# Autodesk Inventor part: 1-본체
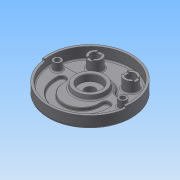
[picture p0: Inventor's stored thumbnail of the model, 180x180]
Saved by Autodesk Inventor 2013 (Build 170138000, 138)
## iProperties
Created: 2015-06
Part Number: 1-본체
Material: 일반
Document SubType Name: Modeling
Designer: Administrator
Density: 1 g/cm^3
Author: Administrator
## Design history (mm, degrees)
sketch "스케치1"
  geometry: C1 r 95 at (0, 0); 1 further point
  constraints: 1 centre point, 1 coincident
  dimensions: "d0" = 190 diameter of C1
extrude "돌출1" new body sketch "스케치1" distance "d2" = 32; taper "d3" = 0 deg
sketch "스케치2"
  geometry: C1 r 95 at (0, 0) reference; C2 r 90 at (0, 0)
  constraints: 1 centre point, 1 coincident
  dimensions: "d4" = 180 diameter of C2
extrude "돌출2" cut sketch "스케치2" distance "d6" = 18; taper "d7" = 0 deg
sketch "스케치3"
  geometry: L1 (-75.657, 16)-(-45.033, 16); L2 (45.033, 16)-(75.657, 16); A1 r 90 centre (0, 0) between (85.114, 29.25) and (-85.114, 29.25); A2 r 42 centre (0, 0) between (36.373, 21) and (-36.373, 21); A3 r 10 centre (-75.657, 26) between (-85.114, 29.25) and (-75.657, 16); A4 r 10 centre (-45.033, 26) between (-45.033, 16) and (-36.373, 21); A5 r 10 centre (45.033, 26) between (36.373, 21) and (45.033, 16); A6 r 10 centre (75.657, 26) between (75.657, 16) and (85.114, 29.25); 5 further points
  constraints: 16 point on circle, 8 tangent, 6 centre point, 4 end point, 4 point on line, 3 equal radius, 2 coincident, 2 horizontal, 1 collinear, 3 other
  dimensions: "d10" = 84 diameter of A2; "d11" = 16 distance from line of L2 point (0, 0); "d12" = 10 radius of A3
extrude "돌출3" cut sketch "스케치3" distance "d13" = 7; taper "d14" = 0 deg
sketch "스케치4"
  geometry: C1 r 15 at (-40, 52); C2 r 15 at (40, 52); A1 r 42 centre (0, 0) between (36.373, 21) and (-36.373, 21) reference
  constraints: 2 centre point, 1 equal radius, 1 horizontal alignment
  dimensions: "d15" = 80 distance of C2.centre C1.centre; "d17" = 40 horizontal distance of A1.centre C2.centre; "d18" = 52 vertical distance of A1.centre C1.centre; "d19" = 30 diameter of C1
extrude "돌출4" join sketch "스케치4" stored distance "d20" = 7; taper "d21" = 0 deg
sketch "스케치5"
  geometry: C1 r 15 at (0, 0) reference; C2 r 15 at (80, 0) reference; 3 further points
  constraints: 2 coincident
hole "구멍1" sketch "스케치5" at (0, 0), (80, 0) diameter "d22" = 20; stored, may be unused: countersink angle "d26" = 90 deg, drill point angle "d28" = 118 deg; dims "d23" = 6, "d24" = 4, "d25" = 2, "d27" = 8
sketch "스케치6"
  geometry: L1 (-6, 13.748)-(-6, -13.748); L2 (6, 13.748)-(6, -13.748); L3 (66.252, 6)-(93.748, 6); L4 (66.252, -6)-(93.748, -6); C1 r 10 at (80, 0) reference; A1 r 15 centre (0, 0) between (-6, 13.748) and (-6, -13.748) reference; A2 r 15 centre (80, 0) between (66.252, 6) and (93.748, 6) reference; 1 further point
  constraints: 8 end point, 8 point on circle, 4 parallel, 1 perpendicular, 1 vertical
  dimensions: "d29" = 12 distance between parallel lines of L2 L1; "d30" = 12 distance between parallel lines of L4 L3
extrude "돌출5" cut sketch "스케치6" distance "d31" = 3; taper "d32" = 0 deg
sketch "스케치7"
  geometry: L1 (0, 0)-(95, 0); L2 (0, 0)-(94.075, -13.221); L3 (0, 0)-(-94.075, -13.221); A1 r 95 centre (0, 0) between (95, 0) and (94.075, -13.221) reference
  constraints: 6 end point, 3 point on circle, 1 horizontal
  dimensions: "d33" = 8 deg angle of L1 L3; "d34" = 8 deg angle of L1 L2
extrude "돌출6" cut sketch "스케치7" distance "d35" = 5; taper "d36" = 0 deg
sketch "스케치10"
  geometry: L1 (-45.033, 16)-(-75.657, 16) reference; L2 (0, -19)-(59, -19); L3 (0, -19)-(-59, -19); L4 (59, -19)-(59, -14); L5 (41, -14)-(41, -19); L6 (-41, -19)-(-41, -14); L7 (-59, -14)-(-59, -19); A1 r 42 centre (0, 0) between (36.373, 21) and (-36.373, 21) reference; A2 r 41 centre (0, -19) between (-41, -19) and (41, -19); A3 r 59 centre (0, -19) between (-59, -19) and (59, -19); A4 r 9 centre (50, -14) between (59, -14) and (41, -14); A5 r 9 centre (-50, -14) between (-41, -14) and (-59, -14)
  constraints: 12 end point, 8 point on circle, 8 tangent, 4 centre point, 4 parallel, 2 point on line, 1 coincident, 1 collinear, 1 horizontal alignment, 1 perpendicular, 1 vertical alignment
  dimensions: "d46" = 41 radius of A2; "d47" = 19 distance of A1.centre A3.centre; "d48" = 59 radius of A3; "d49" = 5 distance of L2.end L4.end
extrude "돌출7" cut sketch "스케치10" distance "d50" = 7; taper "d51" = 0 deg
sketch "스케치11"
  geometry: C1 r 35 at (0, 0); A1 r 90 centre (0, 0) between (-85.114, 29.25) and (85.114, 29.25) reference
  constraints: 1 centre point, 1 coincident
  dimensions: "d52" = 70 diameter of C1
extrude "돌출8" join sketch "스케치11" distance "d54" = 10; taper "d55" = -10 deg
sketch "스케치12"
  geometry: C1 r 35 at (0, 0) reference; C2 r 9 at (-74, 0); C3 r 9 at (74, 0)
  constraints: 2 centre point, 2 horizontal alignment
  dimensions: "d56" = 18 diameter of C2; "d58" = 18 diameter of C3; "d59" = 148 distance of C3.centre C2.centre; "d60" = 74 distance of C2.centre C1.centre
extrude "돌출9" join sketch "스케치12" stored distance "d61" = 10; taper "d62" = 0 deg
sketch "스케치13"
  geometry: C1 r 95 at (0, 0) reference; C2 r 26 at (0, 0)
  constraints: 1 centre point, 1 coincident
  dimensions: "d63" = 52 diameter of C2
extrude "돌출10" join sketch "스케치13" distance "d65" = 12; taper "d66" = -15 deg
sketch "스케치14"
  geometry: C1 r 9 at (-74, 0) reference; C2 r 9 at (74, 0) reference; 2 further points
  constraints: 2 coincident
hole "구멍2" sketch "스케치14" at (-74, 0), (74, 0) diameter "d67" = 11; stored, may be unused: countersink angle "d71" = 90 deg, drill point angle "d73" = 118 deg; dims "d68" = 6, "d69" = 18, "d70" = 11, "d72" = 8
hole "구멍3" diameter "d76" = 23; stored, may be unused: countersink angle "d80" = 90 deg, drill point angle "d82" = 118 deg; dims "d74" = 10, "d75" = 10, "d77" = 6, "d78" = 50, "d79" = 15, "d81" = 8
sketch "스케치15"
  geometry: C1 r 95 at (0, 0) reference; C2 r 68 at (0, 0)
  constraints: 1 centre point, 1 coincident, 1 other
  dimensions: "d83" = 136 diameter of C2
feature "엠보싱1" sketch "스케치15" dims "d10" = 84, "d11" = 16, "d12" = 10, "d85" = 0.5, "d86" = 0
fillet "모깎기1" dims "d87" = 5, "d88" = 0.3, "d89" = 1
chamfer "모따기1" distance "d90" = 1; stored, may be unused: second distance "d91" = 2, angle "d92" = 45 deg
fillet "모깎기2" dims "d93" = 3
node "솔리드1"
other parameters: "d8" = 16, "d39" = 59, "d44" = 59
